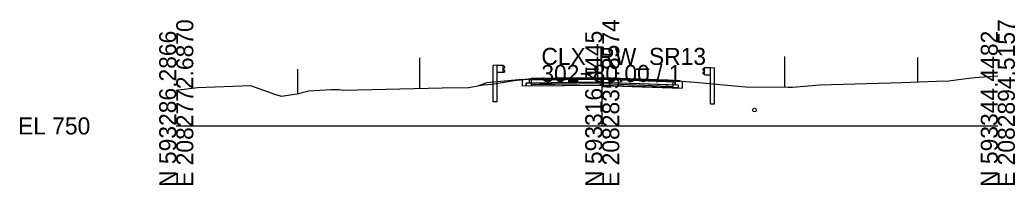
# Model space of a CAD drawing. Extents: x -26 to 2138, y -10 to 4518.
# Drawn here: x -25.7 to 137.8, y 3490.3 to 3517.4 of the extents above; entities that cross this region are included whole.
import ezdxf

# ---------------------------------------------------------------- set-up
doc = ezdxf.new("R2010")
doc.units = 0
for name, color, linetype in [('GK_Cells', 7, 'Continuous'), ('MD_P_Surface_Aggregate_Base', 7, 'Continuous'), ('MD_P_Surface_Asphalt_Concrete_Base', 7, 'Continuous'), ('MD_P_Surface_Asphalt_Concrete_Intermediate_Course', 7, 'Continuous'), ('MD_P_Surface_Asphalt_Concrete_Surface_Course', 7, 'Continuous'), ('MD_X_Asphalt_Pavement', 7, 'Continuous'), ('RD_P_Cells', 7, 'Continuous'), ('RW_P_Esmt_SH', 7, 'Continuous'), ('RW_X_Esmt_SH', 7, 'Continuous'), ('SC_Scratch1', 7, 'Continuous'), ('UT_X_Water', 7, 'Continuous'), ('XS_P_Finished_Grade', 7, 'Continuous'), ('XS_P_Subgrade', 7, 'Continuous'), ('XS_X_Ground_Line', 7, 'Continuous')]:
    doc.layers.add(name, color=color, linetype=linetype)

msp = doc.modelspace()

# ---------------------------------------------------------------- linework, layer by layer
at = {"layer": 'GK_Cells'}
for p, q in [((70, 3500), (70, 3510)), ((0, 3500), (70, 3500)), ((70, 3500), (135, 3500))]:
    msp.add_line(p, q, dxfattribs=at)
at = {"layer": 'MD_P_Surface_Aggregate_Base'}
for points in [[(70, 3506.65), (57.52, 3506.53), (57.52, 3507.03), (70, 3507.15), (70, 3506.65)], [(82.46, 3506.72), (82.46, 3506.22), (70, 3506.65), (70, 3507.15), (82.46, 3506.72)]]:
    msp.add_lwpolyline(points, dxfattribs=at)
at = {"layer": 'MD_P_Surface_Asphalt_Concrete_Base'}
for points in [[(70, 3507.15), (58.02, 3507.03), (58.02, 3507.53), (70, 3507.65), (70, 3507.15)], [(70, 3507.65), (70, 3507.15), (81.96, 3506.73), (81.96, 3507.23)]]:
    msp.add_lwpolyline(points, dxfattribs=at)
at = {"layer": 'MD_P_Surface_Asphalt_Concrete_Intermediate_Course'}
for points in [[(70, 3507.65), (70, 3507.8)], [(70, 3507.8), (70, 3507.65)]]:
    msp.add_lwpolyline(points, dxfattribs=at)
at = {"layer": 'MD_P_Surface_Asphalt_Concrete_Surface_Course'}
for points in [[(70, 3507.8), (70, 3507.9)], [(70, 3507.9), (70, 3507.8)]]:
    msp.add_lwpolyline(points, dxfattribs=at)
at = {"layer": 'MD_X_Asphalt_Pavement'}
msp.add_lwpolyline([(62.27, 3507.83), (59.64, 3507.8), (58.5, 3507.75), (58.34, 3507.74), (58.34, 3506.78), (58.5, 3506.79), (59.64, 3506.84), (62.27, 3506.87), (70.05, 3506.94), (72.93, 3506.82), (80.83, 3506.54), (81.48, 3506.49), (81.63, 3506.48), (81.63, 3507.44), (81.48, 3507.45), (80.83, 3507.5), (72.93, 3507.78), (70.05, 3507.9), (62.27, 3507.83)], dxfattribs=at)
at = {"layer": 'RD_P_Cells'}
for p, q in [((52.1, 3509.89), (52.05, 3509.86)), ((52.05, 3503.97), (52.05, 3509.86)), ((52.64, 3509.97), (52.1, 3509.89)), ((52.72, 3509.93), (52.64, 3509.97)), ((53.72, 3509.93), (52.72, 3509.93)), ((52.72, 3503.97), (52.72, 3509.93)), ((53.72, 3508.74), (53.72, 3509.93)), ((53.81, 3509.83), (53.72, 3509.84)), ((53.76, 3509.44), (53.97, 3509.59)), ((53.97, 3509.71), (53.81, 3509.83)), ((86.53, 3509.35), (86.69, 3509.46)), ((86.69, 3509.46), (86.78, 3509.48)), ((86.78, 3508.37), (86.78, 3509.56)), ((86.78, 3509.56), (87.78, 3509.56)), ((87.78, 3509.56), (87.86, 3509.6)), ((87.78, 3503.6), (87.78, 3509.56)), ((87.86, 3509.6), (88.4, 3509.52)), ((88.4, 3509.52), (88.45, 3509.5)), ((88.45, 3503.6), (88.45, 3509.5)), ((53.72, 3508.74), (52.72, 3508.74)), ((53.72, 3508.82), (53.81, 3508.84)), ((53.73, 3509.33), (53.73, 3509.38)), ((53.73, 3509.29), (53.73, 3509.33)), ((53.97, 3509.08), (53.76, 3509.22)), ((53.81, 3508.84), (53.97, 3508.95)), ((86.74, 3509.08), (86.53, 3509.22)), ((86.53, 3508.71), (86.74, 3508.86)), ((86.69, 3508.47), (86.53, 3508.59)), ((86.78, 3508.46), (86.69, 3508.47)), ((86.77, 3508.97), (86.77, 3509.01)), ((86.77, 3508.92), (86.77, 3508.97)), ((86.78, 3508.37), (87.78, 3508.37)), ((52.72, 3503.97), (52.05, 3503.97)), ((87.78, 3503.6), (88.45, 3503.6))]:
    msp.add_line(p, q, dxfattribs=at)
for points in [[(53.74, 3509.39), (53.74, 3509.27), (53.73, 3509.27), (53.73, 3509.39)], [(53.74, 3509.36), (53.74, 3509.3), (53.76, 3509.3), (53.76, 3509.36)], [(86.76, 3509), (86.76, 3508.94), (86.74, 3508.94), (86.74, 3509)], [(86.76, 3509.03), (86.76, 3508.91), (86.77, 3508.91), (86.77, 3509.03)]]:
    msp.add_lwpolyline(points, close=True, dxfattribs=at)
for centre, start, end in [((53.81, 3509.38), 124.962, 180), ((53.92, 3509.65), 304.962, 54.7677), ((53.81, 3509.28), 180, 235.038), ((53.92, 3509.01), 304.962, 54.7677), ((86.58, 3509.29), 125.2323, 235.038), ((86.58, 3508.65), 125.2323, 235.038), ((86.69, 3509.01), 0, 55.038), ((86.69, 3508.92), 304.962, 0)]:
    msp.add_arc(centre, 0.0781, start, end, dxfattribs=at)
at = {"layer": 'RW_P_Esmt_SH'}
for p, q in [((121.87, 3507.23), (121.87, 3511.23)), ((20, 3505.3), (20, 3509.3))]:
    msp.add_line(p, q, dxfattribs=at)
at = {"layer": 'RW_X_Esmt_SH'}
for p, q in [((40, 3506.16), (40, 3511.16)), ((100, 3506.37), (100, 3511.37))]:
    msp.add_line(p, q, dxfattribs=at)
at = {"layer": 'SC_Scratch1'}
for p, q in [((56.84, 3507.63), (58.34, 3507.78)), ((70, 3507.9), (58.34, 3507.78)), ((70, 3507.8), (58.34, 3507.68)), ((58.34, 3507.78), (58.34, 3507.53)), ((70, 3507.9), (81.63, 3507.49)), ((70, 3507.8), (81.63, 3507.39)), ((70, 3507.15), (57.51, 3507.03)), ((57.51, 3507.03), (57.51, 3506.53)), ((70, 3507.65), (58.01, 3507.53)), ((58.01, 3507.53), (58.01, 3507.03)), ((70, 3507.65), (81.96, 3507.23)), ((70, 3507.15), (82.46, 3506.72)), ((81.63, 3507.49), (81.63, 3507.24)), ((81.63, 3507.49), (83.13, 3507.34)), ((81.96, 3507.23), (81.96, 3506.73)), ((82.46, 3506.72), (82.46, 3506.22))]:
    msp.add_line(p, q, dxfattribs=at)
at = {"layer": 'UT_X_Water'}
msp.add_circle((95, 3502.59), 0.3, dxfattribs=at)
at = {"layer": 'XS_P_Finished_Grade'}
for p, q in [((51.05, 3507.06), (49.69, 3506.6)), ((56.84, 3507.63), (51.05, 3507.06)), ((83.13, 3507.34), (84.3, 3507.23))]:
    msp.add_line(p, q, dxfattribs=at)
at = {"layer": 'XS_P_Subgrade'}
for p, q in [((56.84, 3507.63), (56.84, 3506.52)), ((70, 3506.65), (56.84, 3506.52)), ((70, 3506.65), (83.13, 3506.19)), ((83.13, 3507.34), (83.13, 3506.19))]:
    msp.add_line(p, q, dxfattribs=at)
at = {"layer": 'XS_X_Ground_Line'}
msp.add_lwpolyline([(0, 3505.87), (3.47, 3506.29), (12.18, 3506.62), (16.33, 3505.13), (16.34, 3505.13), (17.26, 3504.87), (19.89, 3505.27), (21.77, 3505.78), (25.42, 3505.95), (25.93, 3505.98), (26.09, 3505.98), (26.26, 3505.99), (26.53, 3505.97), (26.71, 3505.95), (27.06, 3505.92), (27.46, 3505.88), (43.68, 3506.24), (48.05, 3506.31), (50.41, 3506.73), (51.9, 3506.86), (55.19, 3507.41), (55.92, 3507.51), (55.98, 3507.52), (58.34, 3507.74), (58.5, 3507.75), (59.64, 3507.8), (62.27, 3507.83), (70.05, 3507.9), (72.93, 3507.78), (80.83, 3507.5), (81.48, 3507.45), (81.63, 3507.44), (85.22, 3507.16), (89.39, 3506.79), (93.53, 3506.4), (100.56, 3506.37), (101.26, 3506.37), (105.75, 3506.75), (119.26, 3507.14), (124.9, 3507.34), (126.97, 3507.41), (128.18, 3507.57), (129.82, 3507.78), (131.23, 3507.95), (135, 3508.22)], dxfattribs=at)

# ---------------------------------------------------------------- texts
msp.add_text('-', height=0.0001).set_placement((0, 3500))
at = {"layer": 'GK_Cells'}
for s, p in [('E 2082772.6870', (2.8, 3490)), ('E 2082835.8574', (72.8, 3490)), ('E 2082894.5157', (137.8, 3490)), ('N 593286.2866', (0, 3490)), ('N 593316.4445', (70, 3490)), ('N 593344.4482', (135, 3490))]:
    msp.add_text(s, height=2.8, rotation=90, dxfattribs=at).set_placement(p)
for s, p in [('CLX_RW_SR13', (60, 3510)), ('302+80.00 / 1', (60, 3507.2)), ('EL 750', (-26, 3498.6))]:
    msp.add_text(s, height=2.8, dxfattribs=at).set_placement(p)

doc.saveas('drawing.dxf')
